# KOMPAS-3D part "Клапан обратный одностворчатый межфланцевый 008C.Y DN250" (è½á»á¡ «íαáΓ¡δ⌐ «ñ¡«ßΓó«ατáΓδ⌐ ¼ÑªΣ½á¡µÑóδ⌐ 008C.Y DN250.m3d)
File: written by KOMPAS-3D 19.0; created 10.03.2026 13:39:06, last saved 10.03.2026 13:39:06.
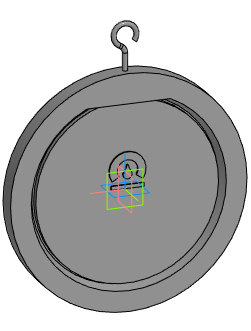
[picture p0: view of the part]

Document properties: Автор: Евгений; Полное имя файла: E:\Dendor\3D для проектировщиков\5.1 Тип 008C. Клапан обратный одностворчатый межфланцевый\stp_Клапан обратный одностворчатый межфланцевый 008C.Y\Клапан обратный одностворчатый межфланцевый 008C.Y DN250.m3d

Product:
- Part/product: Клапан обратный одностворчатый межфланцевый 008C.Y DN250

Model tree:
1. Операция без истории:1  (labels: Клапан обратный одностворчатый межфланцевый 008C.Y DN250)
